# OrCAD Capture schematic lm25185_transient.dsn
size C
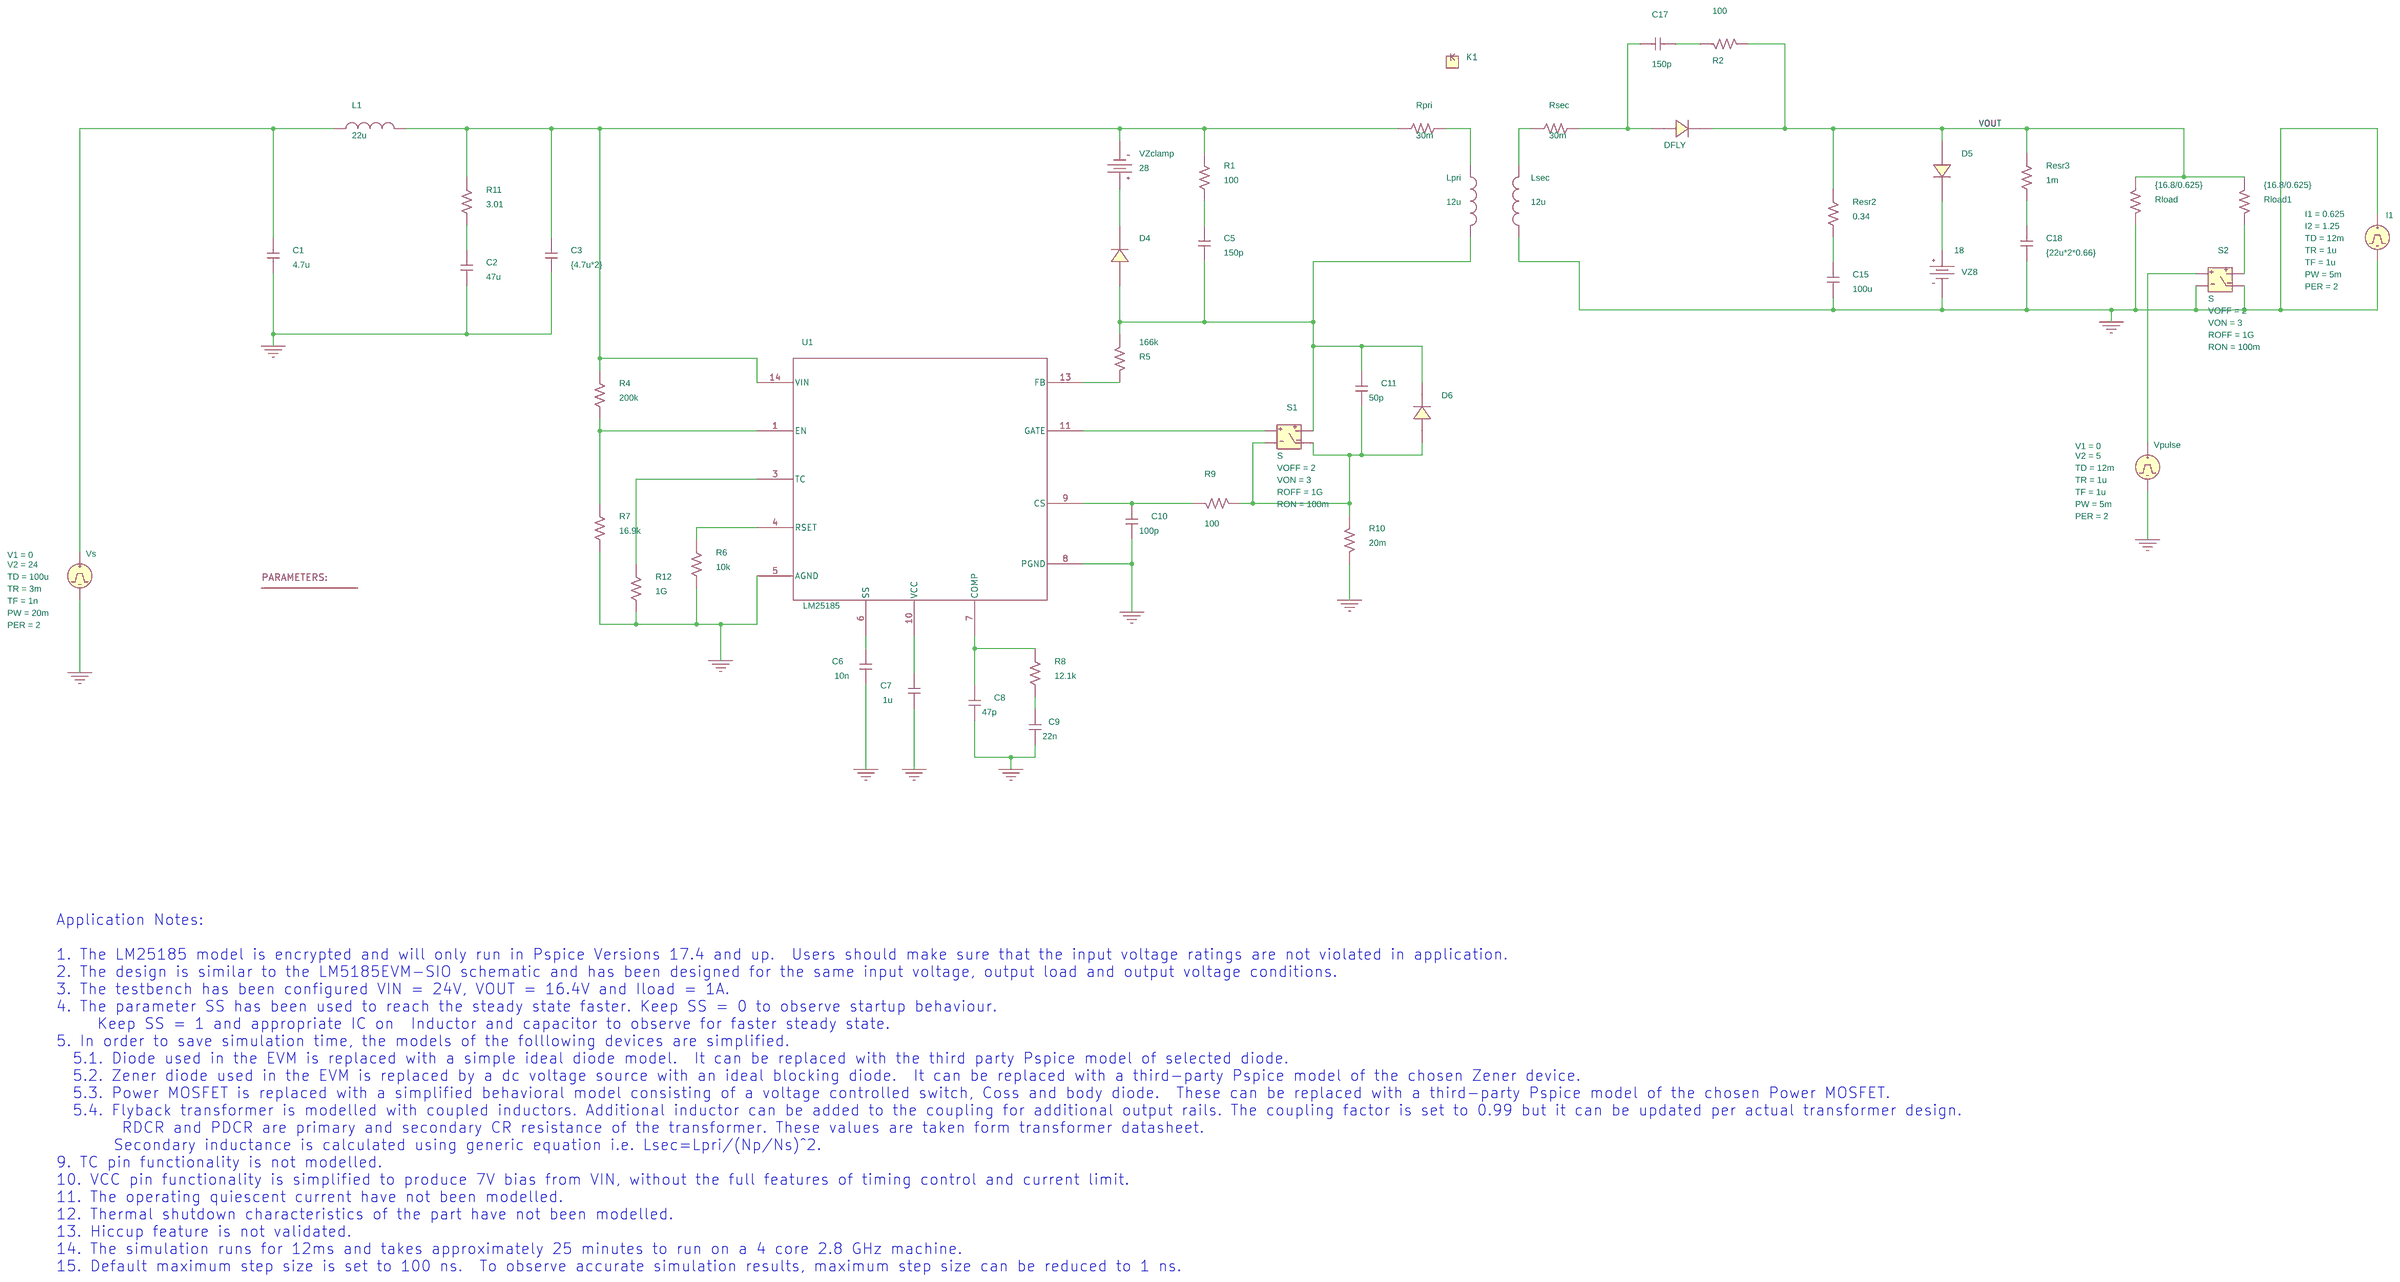
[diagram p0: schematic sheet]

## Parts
1  PARAM
C1  4.7u  [RAD/CK05]
C2  47u  [RAD/CK05]
C3  {4.7u*2}  [RAD/CK05]
C5  150p  [RAD/CK05]
C6  10n  [RAD/CK05]
C7  1u  [RAD/CK05]
C8  47p  [RAD/CK05]
C9  22n  [RAD/CK05]
C10  100p  [RAD/CK05]
C11  50p  [RAD/CK05]
C15  100u  [RAD/CK05]
C17  150p  [RAD/CK05]
C18  {22u*2*0.66}  [RAD/CK05]
D4  D_D1
D5  D_D1
D6  D_D1
DFLY  D_D
I1  IPULSE
K1  Kbreak
L1  22u  [DISC/.350x.175/LS.200x.100/.034]
Lpri  12u  [DISC/.350x.175/LS.200x.100/.034]
Lsec  12u  [DISC/.350x.175/LS.200x.100/.034]
R1  100  [AX/RC05]
R2  100  [AX/RC05]
R4  200k  [AX/RC05]
R5  166k  [AX/RC05]
R6  10k  [AX/RC05]
R7  16.9k  [AX/RC05]
R8  12.1k  [AX/RC05]
R9  100  [AX/RC05]
R10  20m  [AX/RC05]
R11  3.01  [AX/RC05]
R12  1G  [AX/RC05]
Resr2  0.34  [AX/RC05]
Resr3  1m  [AX/RC05]
Rload  {16.8/0.625}  [AX/RC05]
Rload1  {16.8/0.625}  [AX/RC05]
Rpri  30m  [AX/RC05]
Rsec  30m  [AX/RC05]
S1  S
S2  S
U1  LM25185
Vpulse  VPULSE
Vs  VPULSE
VZ8  VDC
VZclamp  VDC

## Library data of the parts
1 = PARAM
C1-C3 C5-C11 C15 C17 C18 = C
D4-D6 = D_D1
DFLY = D_D: PSpiceTemplate: D^@REFDES %1 %2 @MODEL
I1 = IPULSE: I1: 0.625; I2: 1.25; PER: 2; PW: 5m; TD: 12m; TF: 1u; TR: 1u
K1 = kbreak: L1: Lpri; L2: Lsec; PSpiceTemplate: Kn^@REFDES L^@L1 ?L2|L^@L2| ?L3|L^@L3| ?L4|L^@L4| ?L5|L^@L5| ?L6|L^@L6| @COUPLING
L1 Lpri Lsec = L
R1 R2 R4-R12 Resr2 Resr3 Rload Rload1 = R
Rpri Rsec = r
S1 S2 = S: ROFF: 1G; RON: 100m; VOFF: 2; VON: 3
U1 = LM25185_Trans
Vpulse = VPULSE: PER: 2; PW: 5m; TD: 12m; TF: 1u; TR: 1u; V1: 0; V2: 5
Vs = VPULSE: PER: 2; PW: 20m; TD: 100u; TF: 1n; TR: 3m; V1: 0; V2: 24
VZ8 = VDC: DC: 18
VZclamp = VDC: DC: 28

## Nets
0: C1.1 C2.1 C3.1 C6.1 C7.1 C8.1 C9.1 C10.1 C15.1 C18.1 I1.1(+) I1.2(-) Lsec.1 R6.2 R7.2 R10.2 R12.2 Rload.2 S2.1(2) S2.3(4) U1.5(AGND) U1.8(PGND) Vpulse.2(-) Vs.2(-) VZ8.1(-)
VOUT: D5.2(A) DFLY.2 R2.2 Resr2.1 Resr3.1 Rload.1 Rload1.1
N00910: C1.2 L1.1 Vs.1(+)
N00928: C3.2 L1.2 R1.1 R4.1 R11.1 Rpri.1 U1.14(VIN) VZclamp.1(-)
N01114: R4.2 R7.1 U1.1(EN)
N01204: R6.1 U1.4(RSET)
N01904: C7.2 U1.10(VCC)
N02498: C8.2 R8.1 U1.7(COMP)
N02572: C9.2 R8.2
N03053: C11.1 D6.2(A) R9.2 R10.1 S1.1(2) S1.3(4)
N03079: C10.2 R9.1 U1.9(CS)
N05318: C5.2 R1.2
N05324: D4.1(C) VZclamp.0(+)
N05348: C5.1 C11.2 D4.2(A) D6.1(C) Lpri.2 R5.1 S1.2(3)
N05392: Lpri.1 Rpri.2
N05402: Lsec.2 Rsec.1
N05410: C17.2 DFLY.1 Rsec.2
N06647: S1.0(1) U1.11(GATE)
N06673: R5.2 U1.13(FB)
N07916: D5.1(C) VZ8.0(+)
N10920: C2.2 R11.2
N11966: R12.1 U1.3(TC)
N12302: C6.2 U1.6(SS)
N13601: C15.2 Resr2.2
N14065: C17.1 R2.1
N18703: Rload1.2 S2.2(3)
N19055: S2.0(1) Vpulse.1(+)
N19989: C18.2 Resr3.2

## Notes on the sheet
- Application Notes:
  1. The LM25185 model is encrypted and will only run in Pspice Versions 17.4 and up.  Users should make sure that the input voltage ratings are not violated in application.
  2. The design is similar to the LM5185EVM-SIO schematic and has been designed for the same input voltage, output load and output voltage conditions.
  3. The testbench has been configured VIN = 24V, VOUT = 16.4V and Iload = 1A.
  4. The parameter SS has been used to reach the steady state faster. Keep SS = 0 to observe startup behaviour.
       Keep SS = 1 and appropriate IC on  Inductor and capacitor to observe for faster steady state.
  5. In order to save simulation time, the models of the folllowing devices are simplified.
    5.1. Diode used in the EVM is replaced with a simple ideal diode model.  It can be replaced with the third party Pspice model of selected diode.
    5.2. Zener diode used in the EVM is replaced by a dc voltage source with an ideal blocking diode.  It can be replaced with a third-party Pspice model of the chosen Zener device.
    5.3. Power MOSFET is replaced with a simplified behavioral model consisting of a voltage controlled switch, Coss and body diode.  These can be replaced with a third-party Pspice model of the chosen Power MOSFET.
    5.4. Flyback transformer is modelled with coupled inductors. Additional inductor can be added to the coupling for additional output rails. The coupling factor is set to 0.99 but it can be updated per actual transformer design.
          RDCR and PDCR are primary and secondary CR resistance of the transformer. These values are taken form transformer datasheet.
         Secondary inductance is calculated using generic equation i.e. Lsec=Lpri/(Np/Ns)^2.
  9. TC pin functionality is not modelled.
  10. VCC pin functionality is simplified to produce 7V bias from VIN, without the full features of timing control and current limit.
  11. The operating quiescent current have not been modelled.
  12. Thermal shutdown characteristics of the part have not been modelled.
  13. Hiccup feature is not validated.
  14. The simulation runs for 12ms and takes approximately 25 minutes to run on a 4 core 2.8 GHz machine.
  15. Default maximum step size is set to 100 ns.  To observe accurate simulation results, maximum step size can be reduced to 1 ns.
